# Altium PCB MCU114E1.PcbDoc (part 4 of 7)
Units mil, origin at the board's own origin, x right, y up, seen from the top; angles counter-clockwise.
Board outline 4163.97 x 2322.49 mil, 8 copper layers (Top Layer, GND 2, Signal Layer 3, Power 4, Power 5, Signal Layer 6, GND 7, Bottom), stack 61.2 mil thick; 444 components, 416 nets, 1812 pads, 989 vias.
Unrouted connection lines stored in the file: 3.
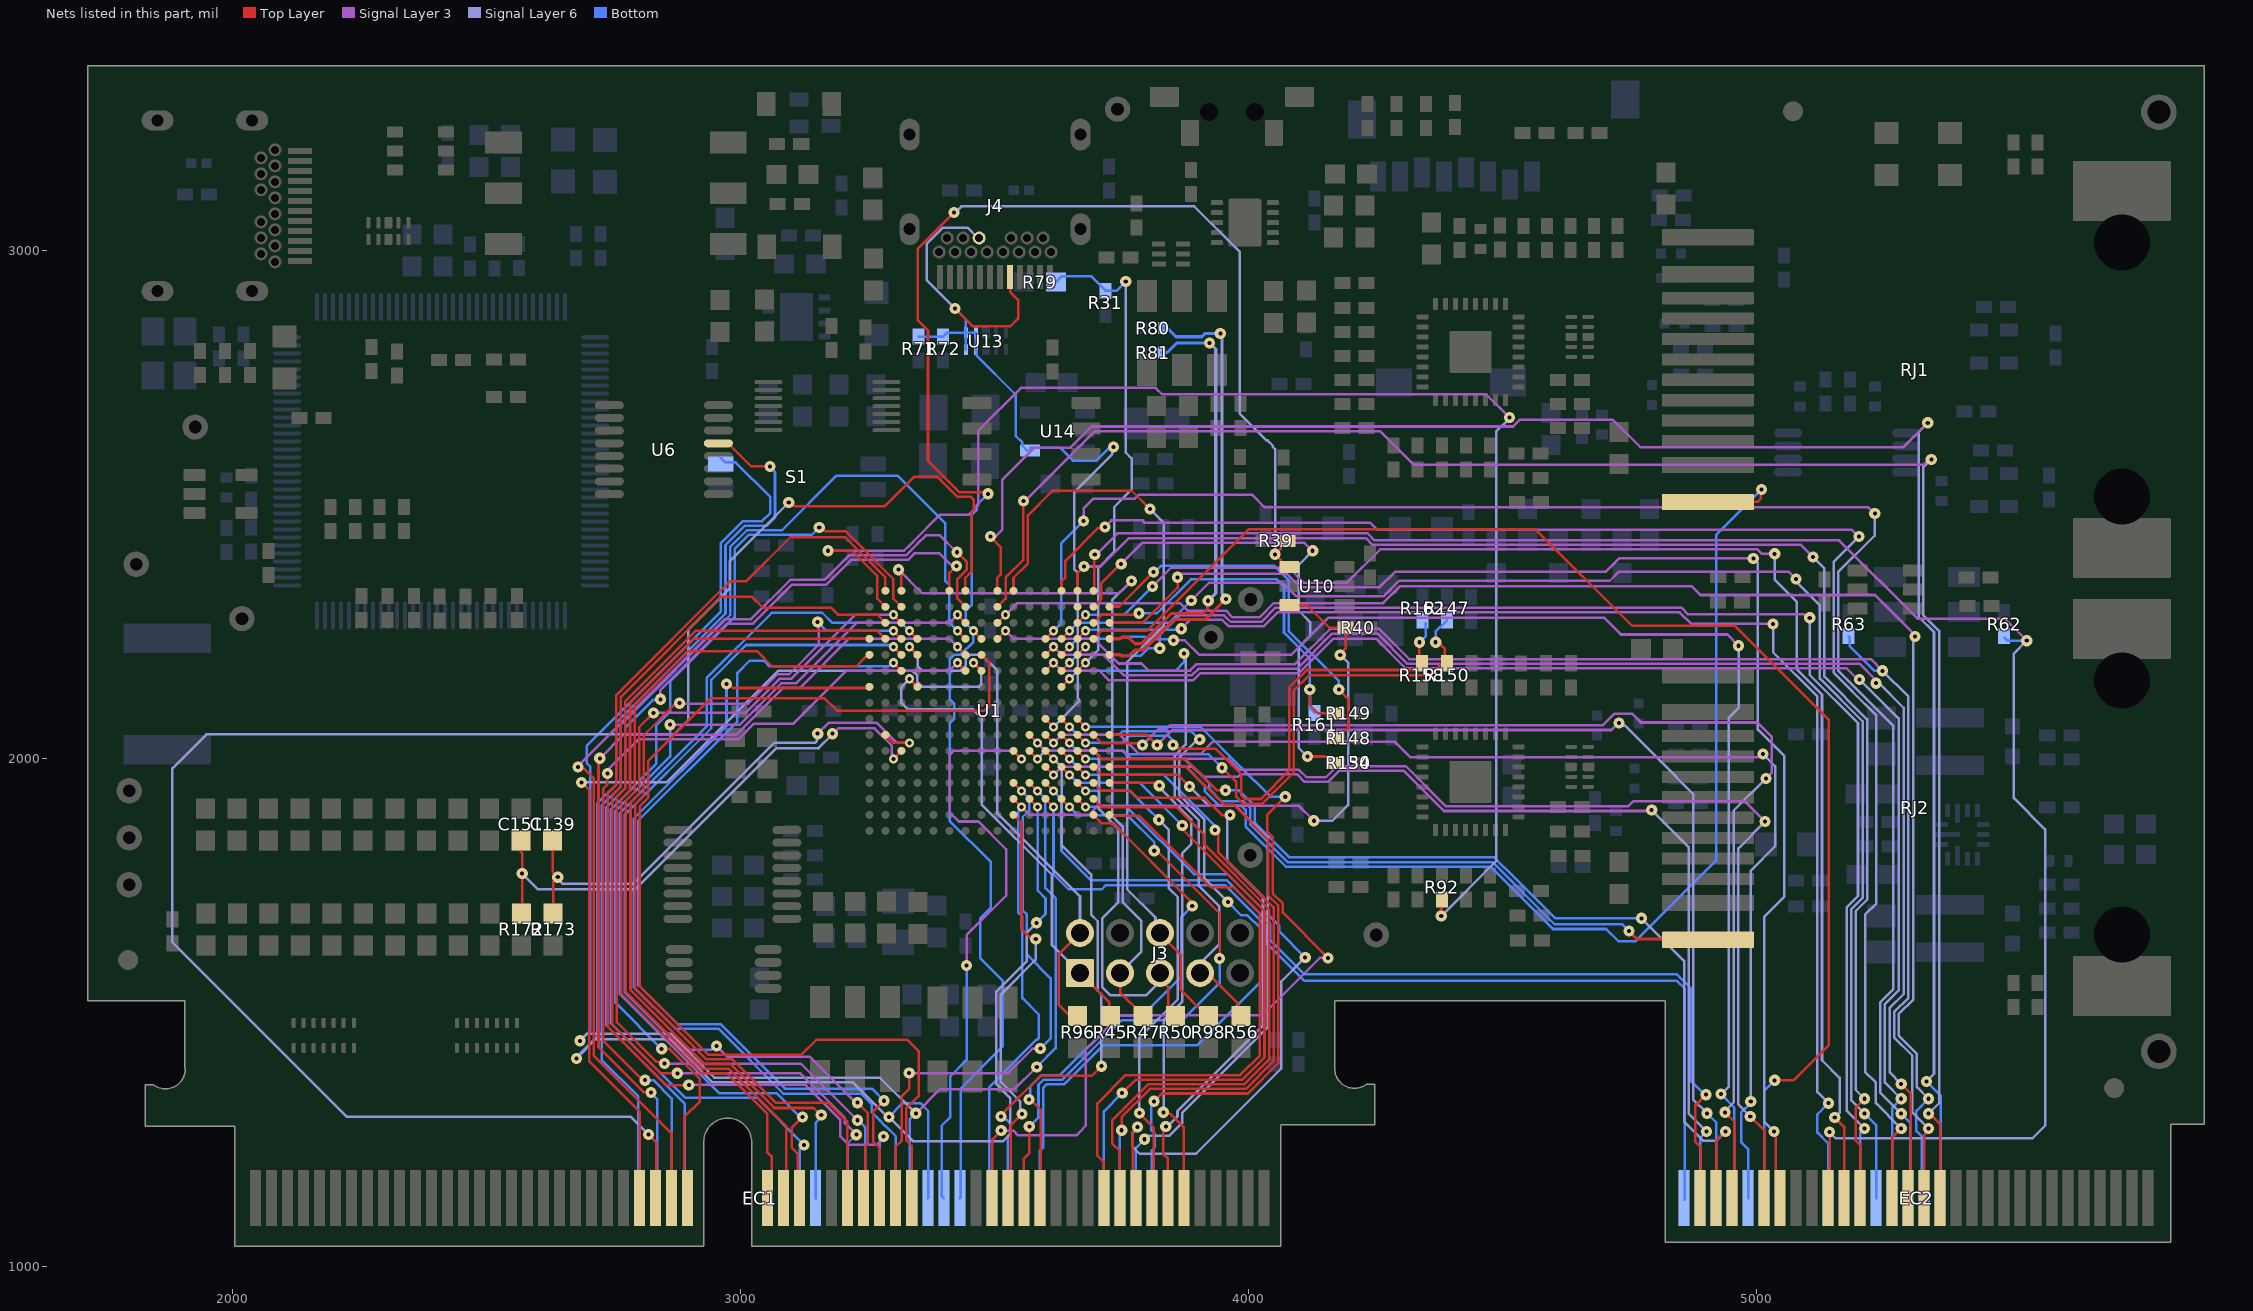
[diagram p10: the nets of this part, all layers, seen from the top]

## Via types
v1: diameter 22, hole 8, Top Layer to Bottom, tented both sides, 818 vias
v2: diameter 18, hole 8, Top Layer to Bottom, tented both sides, 153 vias
v3: diameter 19.68, hole 7.87, Top Layer to Bottom, 18 vias

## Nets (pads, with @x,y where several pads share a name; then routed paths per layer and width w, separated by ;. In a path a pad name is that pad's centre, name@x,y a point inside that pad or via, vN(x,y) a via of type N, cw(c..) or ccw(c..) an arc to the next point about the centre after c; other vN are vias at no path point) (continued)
MCU_C10C11_N: C139.1 R173.1 U1.K2 | length 1059.9
  Top Layer w4.9: C139.1@2630.06,1839.38 2630.06,1777.12 v1(2640.31,1766.88) 2631.04,1757.6 R173.1@2631.04,1695.94 ; U1.K2@3285.09,2047.04 3301.08,2031.06 v2(3332.6,2031.06)
  Signal Layer 3 w4.9: v1(3151.82,2049.25) 3173.14,2070.57 3268.21,2070.57 3307.73,2031.06 v2(3332.6,2031.06)
  Signal Layer 6 w4.9: v1(2640.31,1766.88) 2640.31,1763.7 2649.67,1754.34 2789.09,1754.34 3066.57,2031.82 3089.6,2031.82 3147.36,2031.82 3150.23,2034.69 3150.23,2047.67 v1(3151.82,2049.25)
MCU_C10C11_P: C151.1 R172.1 U1.L3 | length 1079.9
  Top Layer w4.9: C151.1@2567.97,1839.38 2567.97,1816.69 2570.31,1814.36 v1(2570.31,1773.88) 2570.31,1697.31 R172.1@2568.95,1695.94
  Top Layer w5: v2(3300.84,1999.8) U1.L3@3316.59,2015.55
  Signal Layer 3 w4.9: v1@3180.82,2048.25 3192.24,2059.67 3263.7,2059.67 3297.81,2025.56 3297.81,2009.22 3298.34,2008.69 3298.34,2003.35 3297.81,2002.83 v2(3300.84,1999.8)
  Signal Layer 6 w4.9: v1(2570.31,1773.88) 2600.74,1743.44 2793.61,1743.44 3071.08,2020.92 3085.09,2020.92 3153.48,2020.92 v1@3180.82,2048.25
  other v1: 3180.82,2049.25
MCU_D_N: R81.2 U1.D16 | length 864
  Top Layer w6.1: U1.D16@3726.04,2236.02 3746.91,2236.02 3749.21,2238.32 3764.16,2238.32 3776.16,2226.32 3788.14,2226.32 3847.73,2285.91 3909.36,2285.91 3919.09,2295.64 3919.09,2309.75 v1(3920.19,2310.85)
  Signal Layer 6 w6.1: v1(3920.19,2310.85) 3935,2325.66 3935,2806.1 v1(3922.83,2818.27)
  Bottom w6.1: R81.2@3828.72,2799.19 3839.64,2799.19 3858.72,2818.27 v1(3922.83,2818.27)
MCU_D_P: R80.2 U1.E16 | length 928
  Top Layer w6.1: U1.E16@3726.04,2204.52 3746.91,2204.52 3749.21,2202.22 3764.16,2202.22 3776.16,2214.22 3793.15,2214.22 3852.74,2273.81 3914.37,2273.81 v1(3954.83,2314.27)
  Signal Layer 6 w6.1: v1(3944,2836.98) 3947.1,2833.88 3947.1,2325.79 3954.83,2318.06 v1(3954.83,2314.27)
  Bottom w6.1: R80.2@3829.09,2847.19 3840.02,2847.19 3856.84,2830.37 3907.83,2830.37 3908.08,2830.56 3914.51,2836.98 v1(3944,2836.98)
MCU_GPIO0: EC1.49 U1.F8 | length 1837.1
  Top Layer w5: v1(2687,1953) 2688.3,1953 2702.5,1938.8 2702.5,1404.5 2801.46,1305.54 2801.46,1268.02 2801.33,1267.89 2801.33,1253.39 2801.46,1253.27 EC1.49@2801.46,1135.27 ; v2(3458.32,2188.77) U1.F8@3474.07,2173.03
  Signal Layer 6 w5: v1(2687,1953) 2687.5,1953.5 2854.54,1953.5 3073.82,2172.78 3338.76,2172.78 3347.84,2163.7 3347.84,2151.35 3357.41,2141.78 3411.08,2141.78 3411.33,2141.53 3468.89,2141.53 3473.82,2146.46 3473.82,2173.27 v2(3458.32,2188.77)
MCU_GPIO1: EC1.51 U1.A7 | length 3729.6
  Top Layer w5: v1(2818.83,1260.64) 2834.33,1245.14 2834.33,1135.27 EC1.51@2832.95,1135.27 ; v1(3094.83,2504.27) 3098.99,2504.27 3106.26,2497 3284,2497 3342,2555 3387,2555 3426.23,2515.77 3452.4,2515.77 3459.33,2508.84 3459.33,2490.25 3454.65,2485.56 3454.65,2368.17 3442.57,2356.1 U1.A7@3442.57,2330.51
  Signal Layer 6 w5: v1(2818.83,1260.64) 2784.21,1295.27 2225.26,1295.27 1882,1638.53 1882,1981 1949,2048 2869.15,2048 2897.33,2076.18 2897.33,2253.92 2978.5,2335.09 2978.5,2387.94 v1(3094.83,2504.27)
MCU_GPIO2: EC1.53 U1.B7 | length 2009.5
  Top Layer w5: v1(2680,1984) 2683.25,1980.75 2692.25,1980.75 2711.5,1961.5 2711.5,1415.5 2864.45,1262.55 EC1.53@2864.45,1135.27 ; v1(3425.83,2406.27) 3445.33,2386.77 3445.33,2372.77 3426.54,2353.98 3426.54,2315.04 U1.B7@3442.57,2299.01
  Signal Layer 3 w5: v1(2680,1984) 2680,1985.56 2969.21,2274.77 3002.33,2274.77 3020.85,2274.77 3097.85,2351.77 3165.13,2351.77 3213.63,2400.27 3325.75,2400.27 3348.5,2423.02 3348.5,2423.21 3364.79,2439.5 3392.25,2439.5 3425.48,2406.27 v1(3425.83,2406.27)
MCU_GPIO3: EC1.55 U1.C7 | length 1747.5
  Top Layer w5: v1(2844.83,1429.27) 2860.58,1429.27 2920,1369.85 2920,1325.73 2889,1294.73 2889,1142.21 EC1.55@2895.94,1135.27 ; v2(3426.83,2283.26) U1.C7@3442.57,2267.52
  Signal Layer 3 w5: v1(2861.26,2067.05) 2998.9,2067.05 3080.12,2148.27 3109.08,2148.27 3228.08,2267.27 3410.83,2267.27 v2(3426.83,2283.26)
  Bottom w5: v1(2844.83,1429.27) 2753.73,1520.37 2753.73,1896.82 2861.26,2004.35 v1(2861.26,2067.05)
MCU_GPIO4: EC1.50 U1.D7 | length 2181.2
  Top Layer w5: v2(3426.83,2251.77) U1.D7@3442.57,2236.02
  Bottom w5: EC1.50@2801.46,1135.27 2798.94,1137.78 2798.94,1335.06 2726.73,1407.27 2726.73,1908 2764.5,1945.77 2764.5,2067.41 2979.37,2282.29 2979.37,2416.64 3012.3,2449.57 3081.57,2449.57 3189.24,2557.24 3308.6,2557.24 3403,2462.85 3403,2349.53 3410.83,2341.7 3410.83,2267.76 v2(3426.83,2251.77)
MCU_GPIO5: EC1.52 U1.E7 | length 1755.1
  Top Layer w5: v1(2723.04,2000.8) 2720.5,1998.25 2720.5,1432.5 2808.92,1344.08 2822.92,1344.08 v1(2824,1343) ; v1@2724.26,1999.58 v1@2724.78,2000.1 ; v2(3426.83,2220.27) U1.E7@3442.57,2204.52
  Signal Layer 3 w5: v1(2723.04,2000.8) 2769.51,2047.27 2786.41,2047.27 2991.84,2047.27 3083.84,2139.27 3116.83,2139.27 3213.83,2236.27 3294.42,2236.27 3410.83,2236.27 v2(3426.83,2220.27)
  Bottom w5: v1(2824,1343) 2824,1341.5 2836.33,1329.17 2836.33,1138.65 EC1.52@2832.95,1135.27
MCU_GPIO6: EC1.54 U1.F7 | length 1712.7
  Top Layer w5: v1(2738,1971) 2738,1949.5 2729.5,1941 2729.5,1445.23 2807.26,1367.47 v1(2812.24,1367.47) ; v2(3426.83,2188.77) U1.F7@3442.57,2173.03
  Signal Layer 3 w5: v1(2738,1971) 2738,1977.44 2798.83,2038.27 2995.57,2038.27 3026.57,2069.27 3104.25,2069.27 3208.26,2173.27 3411.33,2173.27 v2(3426.83,2188.77)
  Bottom w5: v1(2812.24,1367.47) 2828.53,1367.47 2864.45,1331.55 EC1.54@2864.45,1135.27
MCU_GPIO7: EC1.56 U1.A6 | length 1876.8
  Top Layer w5: U1.A6@3411.08,2330.51 3411.08,2365.52 v1(3424.83,2379.27)
  Signal Layer 3 w5: v1(2842.32,2116.95) 2842.32,2135.14 2972.94,2265.77 3024.58,2265.77 3101.58,2342.77 3168.86,2342.77 3217.36,2391.27 3329.47,2391.27 3342.2,2404 3391.42,2404 3412.9,2382.52 3421.58,2382.52 v1(3424.83,2379.27)
  Bottom w5: v1(2842.32,2116.95) 2840.92,2115.55 2827.55,2115.55 2773.5,2061.5 2773.5,1942.04 2735.73,1904.27 2735.73,1475.64 2890,1321.37 2890,1141.21 EC1.56@2895.94,1135.27
MCU_GPIO8: EC1.57 U1.D1 | length 1660.3
  Top Layer w5: EC1.57@3053.43,1135.27 3061,1142.84 3061,1217.64 3052.13,1226.51 3052.13,1301.87 2972.73,1381.27 2921.82,1381.27 2765.5,1537.59 2765.5,1921.32 2782.5,1938.32 2782.5,2109.77 2908.75,2236.02 U1.D1@3253.6,2236.02
MCU_GPIO9: EC1.59 U1.E1 | length 1668.2
  Top Layer w5: EC1.59@3084.92,1135.27 3090.33,1140.68 3090.33,1276.4 2976.46,1390.27 2925.55,1390.27 2774.5,1541.32 2774.5,1917.59 2791.5,1934.59 2791.5,2106.04 2897.1,2211.65 3032.66,2211.65 3062.31,2182 3221.83,2182 3227.78,2182.03 3246.06,2200.31 3246.48,2200.31 3250.69,2204.52 U1.E1@3253.6,2204.52
MCU_GPIO10: EC1.61 U1.D4 | length 1816
  Top Layer w5: EC1.61@3116.42,1135.27 3112.83,1138.85 3112.83,1222.27 3100.83,1234.27 3100.83,1238.41 3100.83,1274.27 v1(3121.83,1295.27) ; v2(3332.34,2251.77) U1.D4@3348.09,2236.02
  Bottom w5: v1(3121.83,1295.27) 3117.23,1295.27 3070.5,1342 2958,1342 2762.73,1537.27 2762.73,1893.09 2933.33,2063.69 2933.33,2158.97 3061.63,2287.27 3160.83,2287.27 3180.59,2267.51 3316.59,2267.51 v2(3332.34,2251.77)
MCU_GPIO11: J3.2 R96.2 U1.E4 | length 1047.5
  Top Layer w5: v2(3332.34,2220.27) U1.E4@3348.09,2204.52 ; R96.2@3663.44,1497.68 3644.44,1497.68 3626,1516.12 3626,1615.09 J3.2@3667.96,1657.05
  Signal Layer 6 w5: v2(3332.34,2220.27) 3348.33,2204.27 3348.33,2182.35 3357.41,2173.27 3379.33,2173.27 3433.25,2173.27 3442.82,2182.85 3442.82,2195.19 3451.9,2204.27 3474.32,2204.27 3505.32,2173.27 3505.32,1891.99 3667.96,1729.35 J3.2@3667.96,1657.05
MCU_GPIO12: J3.1 R45.1 U1.G4 | length 931.4
  Top Layer w5: v2(3332.34,2157.28) U1.G4@3348.09,2141.53 ; J3.1@3667.96,1578.31 3725.59,1520.68 R45.1@3725.59,1499.18
  Signal Layer 6 w5: v2(3332.34,2157.28) 3316.59,2141.53 3316.59,2110.03 3329.57,2097.06 3457.83,2097.06 3474.32,2080.57 3474.32,1910.26 3612.83,1771.75 3612.83,1633.44 J3.1@3667.96,1578.31
MCU_GPIO13: J3.3 R47.1 U1.A3 | length 1456
  Top Layer w5: v1(3311,2372) 3316.59,2366.41 U1.A3@3316.59,2330.51 ; R47.1@3787.8,1499.18 3746.7,1540.28 J3.3@3746.7,1578.18 ; J3.3@3746.7,1578.18 cw(c3838.52,1578.31) J3.3@3746.7,1578.31 J3.3@3746.7,1578.18
  Signal Layer 3 w5: v1(3311,2372) 3357.41,2325.59 3744.59,2325.59 v1(3769,2350)
  Signal Layer 6 w5: J3.3@3746.7,1578.31 3788.83,1620.44 3788.83,1680.93 3751.93,1717.83 3751.93,1866.87 3731.31,1887.49 3731.31,2312.31 v1(3769,2350)
MCU_GPIO14: EC1.62 U1.B3 | length 2055.1
  Top Layer w5: v1(3154.83,2455.27) 3158.99,2455.27 3166.26,2448 3206.1,2448 3300.47,2353.63 3300.47,2315.13 U1.B3@3316.59,2299.01
  Bottom w5: EC1.62@3116.42,1135.27 3116.42,1231.85 v1(3124.83,1240.27) 3032.1,1333 2891.1,1333 2744.73,1479.37 2744.73,1900.55 2834,1989.82 2834,2065.44 2861.33,2092.77 2861.33,2151.52 2988.37,2278.56 2988.37,2412.91 3016.03,2440.57 3140.13,2440.57 v1(3154.83,2455.27)
MCU_GPIO15: EC1.64 U1.C3 | length 1783.9
  Top Layer w5: v1(2828.83,2090.27) 2800.5,2061.94 2800.5,1930.86 2783.5,1913.86 2783.5,1545.04 2929.28,1399.27 2980.19,1399.27 3066.69,1312.77 3144.08,1312.77 3157.58,1299.27 v1(3158.83,1299.27) ; v2(3300.84,2283.26) U1.C3@3316.59,2267.52
  Signal Layer 3 w5: v1(2828.83,2090.27) 3009.39,2090.27 3076.39,2157.27 3099.58,2157.27 3225.58,2283.26 v2(3300.84,2283.26)
  Bottom w5: EC1.64@3147.91,1135.27 3148.33,1135.69 3148.33,1284.17 3158.83,1294.67 v1(3158.83,1299.27)
MCU_GPIO16: EC1.67 U1.D3 | length 1825.3
  Top Layer w5: v1(2879.83,2109.27) 2876.58,2106.02 2869.33,2106.02 2809.5,2046.19 2809.5,1927.13 2792.5,1910.13 2792.5,1548.77 2933,1408.27 2983.92,1408.27 3069.42,1322.77 3173.33,1322.77 3209.71,1286.39 3209.71,1136.47 EC1.67@3210.91,1135.27 ; v2(3300.84,2251.77) U1.D3@3316.59,2236.02
  Signal Layer 3 w5: v1(2879.83,2109.27) 2880.83,2108.27 3014.66,2108.27 3072.66,2166.27 3095.85,2166.27 3153.83,2224.25 3153.83,2267.27 v1(3151.83,2269.27)
  Bottom w5: v1(3151.83,2269.27) 3169.33,2251.77 v2(3300.84,2251.77)
MCU_GPIO17: EC1.69 U1.E3 | length 1850.2
  Top Layer w5: v1(3229.83,1323.27) 3250.33,1302.77 3250.33,1242.27 3245.33,1237.27 3245.33,1138.2 EC1.69@3242.4,1135.27 ; v2(3300.84,2220.27) U1.E3@3316.59,2204.52
  Signal Layer 3 w5: v1(2953,1435) 2974.73,1413.27 3136.28,1413.27 3226.28,1323.27 v1(3229.83,1323.27)
  Bottom w5: v1(2953,1435) 2949.57,1435 2941.57,1427 2885.73,1427 2771.73,1541 2771.73,1889.36 2942.33,2059.96 2942.33,2155.24 3010.86,2223.77 3291.41,2223.77 3292.42,2222.76 3298.35,2222.76 v2(3300.84,2220.27)
MCU_GPIO18: EC1.71 U1.F3 | length 1825.1
  Top Layer w5: EC1.71@3273.9,1135.27 3273.9,1233.72 3260.83,1246.79 3260.83,1305.88 v1(3282.03,1327.07) ; v2(3300.84,2188.77) U1.F3@3316.59,2173.03
  Bottom w5: v1(3282.03,1327.07) 3258.33,1350.77 3087.19,1350.77 2960.19,1477.77 2875.72,1477.77 2798.73,1554.76 2798.73,1878.18 2993.83,2073.28 2993.83,2168.83 3017.77,2192.77 3046.08,2192.77 3057.07,2181.78 3291.41,2181.78 3298.41,2188.77 v2(3300.84,2188.77)
MCU_GPIO19: R92.2 U1.B2 | length 2839
  Top Layer w5: v1(3171.83,2409.27) 3219.38,2409.27 3268.97,2359.67 3268.97,2315.13 U1.B2@3285.09,2299.01
  Top Layer w6.25: v1(4378.83,1690.27) 4378.83,1722.1 R92.2@4379.8,1723.06
  Signal Layer 3 w5: v1(3171.83,2409.27) 3321.83,2409.27 3329.06,2416.5 3329.25,2416.5 3339.5,2426.75 3339.5,2426.94 3392.83,2480.27 3449.35,2480.27 3467.33,2498.25 3467.33,2645.33 3551.84,2729.84 3816.77,2729.84 3829.85,2716.77 4467.33,2716.77 v1(4512.83,2671.27)
  Signal Layer 6 w5: v1(4378.83,1690.27) 4486.83,1798.27 4486.83,2643.84 4512.83,2669.84 v1(4512.83,2671.27)
MCU_GPIO20: EC1.68 U1.C2 | length 1983.9
  Top Layer w5: v1(2875.55,1380.99) 2843.11,1380.99 2747.5,1476.6 2747.5,1928.77 2764.5,1945.77 2764.5,2121.5 2962.07,2319.07 3021.85,2319.07 3043.73,2297.19 3178.09,2297.19 3191.63,2283.64 3268.97,2283.64 U1.C2@3285.09,2267.52
  Signal Layer 3 w5: v1(2875.55,1380.99) 3117.74,1380.99 3205.13,1293.6 3205.13,1282.97 v1(3227.81,1260.29)
  Bottom w5: EC1.68@3210.91,1135.27 3210.91,1243.38 v1(3227.81,1260.29)
MCU_GPIO21: EC1.70 U1.D2 | length 1929.6
  Top Layer w5: v1(2850.28,1400.27) 2847.03,1403.52 2834.48,1403.52 2756.5,1481.5 2756.5,1925.04 2773.5,1942.04 2773.5,2113.5 2911.39,2251.39 3269.72,2251.39 U1.D2@3285.09,2236.02
  Signal Layer 3 w5: v1(2850.28,1400.27) 3118.5,1400.27 v1(3230.08,1288.69)
  Bottom w5: v1(3230.08,1288.69) 3231.91,1288.69 3245.31,1275.29 3245.31,1138.18 EC1.70@3242.4,1135.27
MCU_GPIO22: EC1.72 U1.A2 | length 2168.4
  Top Layer w5: v1(2898.25,1358.07) 2897.87,1357.69 2853.69,1357.69 2747,1464.37 2738.5,1472.87 2738.5,1932.5 2755.5,1949.5 2755.5,2125.23 2979.73,2349.46 3011.55,2349.46 3097.85,2435.77 3205.6,2435.77 3285.09,2356.28 U1.A2@3285.09,2330.51
  Signal Layer 3 w5: v1(2898.25,1358.07) 3127.93,1358.07 3196.13,1289.87 3196.13,1257.97 3213.83,1240.27 3268.85,1240.27 3281.36,1252.78 v1(3281.36,1256.8)
  Bottom w5: EC1.72@3273.9,1135.27 3273.9,1249.34 v1(3281.36,1256.8)
MCU_GPIO23: EC1.74 U1.G1 | length 1725.4
  Top Layer w5: v1(2972.4,2146.85) 2977,2146.85 2984.67,2139.19 3245.3,2139.19 3245.58,2139.47 3251.54,2139.47 U1.G1@3253.6,2141.53
  Bottom w5: v1(2972.4,2146.85) 2972.4,2064.58 2789.73,1881.91 2789.73,1551.03 2871.99,1468.77 2956.46,1468.77 3084.46,1340.77 3237.08,1340.77 3258.21,1319.64 3258.21,1304.71 3274.33,1288.58 3274.33,1288.02 3284.58,1277.77 3285.15,1277.77 3305.39,1257.52 EC1.74@3305.39,1135.27
MCU_GPIO24: EC1.75 U1.E8 | length 2224.1
  Top Layer w5: EC1.75@3336.89,1135.27 3336.89,1238.21 3325.83,1249.27 3325.83,1311.76 3350.29,1336.23 3350.29,1424.87 3328.16,1447 3149,1447 3119.27,1417.27 2936.73,1417.27 2801.5,1552.5 2801.5,1906.41 2818.5,1923.4 2818.5,1996.24 2941.03,2118.77 3165.23,2118.77 3189.47,2094.53 3221.64,2094.53 3221.77,2094.66 3480.44,2094.66 3489.44,2103.67 3489.44,2189.15 U1.E8@3474.07,2204.52
MCU_GPIO25: J3.6 R98.2 U1.A10 | length 1531.5
  Top Layer w5: U1.A10@3537.06,2330.51 3537.06,2356.1 3565.33,2384.37 3565.33,2479.02 3613.58,2527.27 3769.83,2527.27 v1(3805.83,2491.27) ; J3.6@3825.44,1657.05 3825.44,1654.68 3866.44,1613.68 3866.44,1545.03 R98.2@3912.29,1499.18
  Signal Layer 6 w5: v1(3805.83,2491.27) 3833,2464.1 3833,2262.56 3760.93,2190.5 3760.93,1743.07 3816.54,1687.46 3816.54,1665.95 J3.6@3825.44,1657.05
MCU_GPIO26: J3.5 R50.1 U1.L11 | length 876.4
  Top Layer w5: U1.L11@3568.56,2015.55 v2(3584.31,1999.8) ; J3.5@3825.44,1578.31 3825.44,1566.91 3841.83,1550.52 3841.83,1505.27 R50.1@3849.42,1497.68
  Signal Layer 6 w5: v2(3584.31,1999.8) 3600.3,2015.79 3694.79,2015.79 3705.31,2005.28 3705.31,1900.77 3742.93,1863.14 3742.93,1717.37 3711.83,1686.27 3711.83,1550.27 3727.83,1534.27 3797.83,1534.27 3825.44,1561.88 J3.5@3825.44,1578.31
MCU_GPIO27: J3.7 R56.1 U1.G13 | length 1096.4
  Top Layer w5: U1.G13@3631.55,2141.53 v2(3647.3,2157.28) ; J3.7@3904.18,1578.31 3913.69,1568.8 3928.3,1568.8 3979.08,1518.02 3979.08,1499.52 R56.1@3984.83,1493.76
  Signal Layer 6 w5: v1(3872.83,2207.27) 3875.92,2204.18 3875.92,2027.61 3854,2005.69 3854,1926.12 3868.33,1911.79 3902,1878.12 3902,1750 3941.83,1710.17 3941.83,1675.27 ; J3.7@3904.18,1578.31 3904.18,1597.06 3941.82,1634.69 3941.82,1675.26
  Bottom w5: v2(3647.3,2157.28) 3662.74,2172.72 3672.31,2172.72 3672.37,2172.78 3830.57,2172.78 ; 3830.58,2172.77 3855.52,2172.77 3872.83,2190.08 v1(3872.83,2207.27)
MCU_GPIO28: EC1.76 S1.2 U1.N11 | length 3163.7
  Top Layer w5: U1.N11@3568.56,1952.55 v2(3584.31,1936.81)
  Signal Layer 3 w5: v1(3344.83,1302.27) 3392.56,1350 3539.19,1350 v1(3582.87,1393.69)
  Signal Layer 6 w5: v1(2684,1445) 2698,1459 2861.83,1459 2948.56,1372.27 3274.83,1372.27 v1(3344.83,1302.27) ; v1(3582.87,1393.69) 3581.87,1392.69 3581.87,1393.69 v1@3582.87,1394.69
  Bottom w5: v1(2684,1445) 2704.5,1465.5 2704.5,1984.25 2697,1991.75 2697,2025.37 2961.37,2289.74 2961.37,2424.09 3004.85,2467.57 3042.59,2467.57 3058.83,2483.8 3058.83,2514.83 2990.44,2583.22 2970.34,2583.22 S1.2@2960.87,2592.69 ; EC1.76@3336.89,1135.27 3333.33,1138.83 3333.33,1290.77 v1(3344.83,1302.27) ; v1(3582.87,1393.69) 3620,1430.81 3620,1725.56 3599.87,1745.69 3599.87,1762.69 ; v2(3584.31,1936.81) 3599.81,1921.31 3599.81,1762.69
MCU_GPIO29: EC1.78 U1.P11 U6.13 | length 3425.7
  Top Layer w5: U6.13@2956.44,2620.69 2958.5,2618.63 2977.74,2618.63 3021.05,2575.32 3057.78,2575.32 v1(3057.83,2575.27) ; U1.P11@3568.56,1921.06 v2(3584.31,1905.31)
  Signal Layer 6 w5: v1(2677,1410) 2715,1448 2860.1,1448 2944.83,1363.27 3221.08,1363.27 3289.08,1295.27 v1(3291.83,1295.27) 3339.33,1247.77 3384.08,1247.77 3516.95,1247.77 3530.61,1261.42 3530.61,1332.43 3503.37,1359.66 3503.37,1542.37 3563.4,1602.4 3563.4,1658.21 v1(3582.37,1677.17)
  Bottom w5: v1(2677,1410) 2677,1413.25 2717.73,1453.98 2717.73,1911.73 2755.5,1949.5 2755.5,2071.14 2970.37,2286.01 2970.37,2420.37 3008.57,2458.57 3051.65,2458.57 3067.83,2474.75 3067.83,2563.84 3057.83,2573.84 v1(3057.83,2575.27) ; v1(3291.83,1295.27) 3318.83,1322.27 3353.84,1322.27 3369.33,1306.78 3369.33,1260.02 3369.33,1136.21 EC1.78@3368.39,1135.27 ; v1(3582.37,1677.17) 3600.06,1694.86 3600.06,1725.04 3584.87,1740.23 3584.87,1760.29 3584.65,1760.51 3584.65,1904.96 v2(3584.31,1905.31)
MCU_GPIO30: EC1.80 U1.L10 | length 1168.6
  Top Layer w5: U1.L10@3537.06,2015.55 v2(3552.81,1999.8)
  Signal Layer 3 w5: v1(3444.83,1593.27) 3444.83,1652.87 3522.83,1730.87 3522.83,1821.54 3467.85,1876.52 3429.52,1876.52 3411.33,1894.71 3411.33,2007.7 3418.92,2015.3 3537.31,2015.3 v2(3552.81,1999.8)
  Bottom w5: EC1.80@3399.88,1135.27 3395.91,1139.24 3395.91,1277.98 3412.83,1294.9 3412.83,1375.27 3444.83,1407.27 v1(3444.83,1593.27)
MCU_GPIO31: EC1.82 R39.1 U1.D8 U10.1 | length 3544.8
  Top Layer w5: v1(3420,3075) 3348.33,3003.33 3348.33,2863.02 3368.83,2842.52 3368.83,2585.9 3429.96,2524.77 3483.33,2524.77 v1(3486.83,2521.27) ; v2(3458.32,2251.77) U1.D8@3474.07,2236.02 ; R39.1@4076.49,2428.69 4072.6,2428.69 4063.29,2419.37 4063.29,2413.73 v1(4051.83,2402.27) 4062.91,2391.19 4062.91,2386.4 4072.22,2377.09 U10.1@4079.74,2377.09
  Signal Layer 6 w5: v1(3420,3075) 3422.66,3075 3434.43,3086.77 3793.56,3086.77 3793.79,3087 3892.75,3087 3982,2997.75 3982,2679 4034.75,2626.25 4036.95,2626.25 4047.2,2616 4047.2,2613.8 4051.83,2609.17 v1(4051.83,2402.27)
  Bottom w5: EC1.82@3431.38,1135.27 3433.33,1137.22 3433.33,1351.41 3515.83,1433.91 3515.83,1563.27 3471.83,1607.27 3471.83,1686.45 3492.59,1707.21 3492.59,1796.51 3411.33,1877.77 3411.33,1911.73 3411.33,2069.21 3420.92,2078.8 3420.92,2108.2 3411.33,2117.79 3411.33,2195.19 3420.9,2204.77 3433.25,2204.77 3458.32,2229.85 v2(3458.32,2251.77) 3442.89,2267.2 3442.89,2276.78 3442.82,2276.84 3442.82,2289.68 3442.89,2289.75 3442.89,2290.31 3454.83,2302.26 3454.83,2479.27 3464.83,2489.27 3464.83,2499.27 v1(3486.83,2521.27)
MCU_GPIO32: EC1.85 U1.J14 | length 1883.2
  Top Layer w5: EC1.85@3495.44,1138.69 3495.44,1251 v1(3512.83,1268.39) ; U1.J14@3663.05,2078.54 v2(3678.79,2062.79) ; v1@4077.83,1931.27 4036,1889.44 4036,1857.35 4047,1846.35 4047,1734.99 4067,1714.99 4067,1697.01 v1(4155.91,1608.1)
  Signal Layer 3 w5: v1(3512.83,1268.39) 3536.71,1268.39 3546.33,1258.77 3660.77,1258.77 3670,1268 3679,1277.77 3679,1427.44 3746.83,1495.27 4026.83,1495.27 4139.66,1608.1 v1(4155.91,1608.1)
  Bottom w5: v2(3678.79,2062.79) 3905.53,2062.79 3986.15,1982.17 3986.15,1981.85 4011.66,1956.33 4011.99,1956.33 4043.05,1925.27 v1@4075.83,1925.27
  other v1: 4071.83,1925.27
MCU_GPIO33: EC1.87 U1.R10 | length 832
  Top Layer w5: EC1.87@3525.87,1135.27 3532.1,1141.5 3532.1,1279.54 v1(3553.83,1301.27) ; U1.R10@3537.06,1889.56 3552.81,1873.81 3552.81,1665.29 v1@3576.83,1641.27
  Signal Layer 6 w5: v1(3553.83,1301.27) 3550.33,1304.77 3550.33,1325.43 3512.37,1363.39 3512.37,1536.37 3580.9,1604.9 v1(3580.9,1645.35)
MCU_GPIO34: EC1.86 R40.1 U1.P10 U10.3 | length 2025.9
  Top Layer w5: U1.P10@3537.06,1921.06 v2(3552.81,1905.31) ; U10.3@4079.74,2302.28 4114.13,2302.28 4158.42,2258 R40.1@4190.66,2258 4190.66,2217.26 4180,2206.6 v1(4180,2204.3)
  Signal Layer 3 w5: v2(3552.81,1905.31) 3568.31,1889.81 3685.22,1889.81 3702.67,1907.27 4098.73,1907.27 v1(4128,1878)
  Signal Layer 6 w5: v1(4128,1878) 4164.56,1878 4195.33,1908.77 4195.33,2188.97 v1(4180,2204.3)
  Bottom w5: EC1.86@3494.37,1135.27 3488.96,1140.68 3488.96,1353.52 3582.62,1447.19 3584.07,1447.19 3587,1450.11 3587,1496.25 3554.4,1528.85 3554.4,1689.79 3546.31,1697.88 3546.31,1895.88 3552.81,1902.38 v2(3552.81,1905.31)
MCU_GPIO35: EC1.73 U1.N10 | length 1107.4
  Top Layer w5: EC1.73@3305.39,1135.27 3305.39,1236.83 3316.83,1248.27 3316.83,1335.27 3331.89,1350.33 v1(3331.89,1381.58) ; U1.N10@3537.06,1952.55 v2(3552.81,1936.81)
  Signal Layer 3 w5: v1(3331.89,1381.58) 3526.58,1381.58 3574.3,1429.3 3589.49,1429.3 v1(3589.87,1429.69)
  Bottom w5: v2(3552.81,1936.81) 3568.31,1921.31 3568.31,1911.73 3568.31,1898.89 3555.31,1885.89 3555.31,1701.61 3563.4,1693.51 3563.4,1665.81 3563.4,1614.6 3610,1568 3610,1449.81 v1(3589.87,1429.69)
MCU_GPIO36: EC2.122 U1.P12 | length 1930.9
  Top Layer w5: U1.P12@3600.06,1921.06 v2(3615.8,1905.31)
  Bottom w5: v2(3615.8,1905.31) 3615.8,1772.76 3645.37,1743.19 3711,1743.19 3719.08,1751.27 3953.56,1751.27 4033,1671.83 4033,1639.27 4109.27,1563 4842.56,1563 4857.87,1547.69 EC2.122@4857.87,1132.69
MCU_GPIO37: EC2.123 U1.N12 | length 1953.6
  Top Layer w5: U1.N12@3600.06,1952.55 v2(3615.8,1936.81) ; EC2.123@4889.05,1138.69 4889.05,1236.05 4878.83,1246.27 4878.83,1317.83 v1(4900,1339)
  Bottom w5: v2(3615.8,1936.81) 3631.55,1921.06 3631.55,1818.76 3689.62,1760.69 3956.87,1760.69 4042,1675.56 4042,1643 4109.31,1575.69 4842.6,1575.69 4870.83,1547.45 4870.83,1364.53 4896.36,1339 v1(4900,1339)
MCU_GPIO38: EC2.124 U1.M12 | length 2069.2
  Top Layer w5: U1.M12@3600.06,1984.05 v2(3615.8,1968.3)
  Signal Layer 3 w5: v2(3615.8,1968.3) 3631.3,1983.8 3891.55,1983.8 3910.58,1964.77 3979.6,1964.77 3984.6,1969.77 4094.54,1969.77 4109.71,1954.61 4155.64,1954.61 4177.31,1976.27 4305.29,1976.27 4384.37,1897.19 4782.75,1897.19 v1@4783.83,1898.27
  Signal Layer 6 w5: v1(4792.83,1899.27) 4865.57,1826.53 4865.57,1301.53 v1(4900.83,1266.27)
  Bottom w5: EC2.124@4887.98,1135.27 4887.98,1253.41 v1(4900.83,1266.27)
MCU_GPIO39: EC1.88 U1.L12 | length 1079
  Top Layer w5: v1(3512.53,1295.76) 3512.53,1298.72 3590,1376.19 3691.19,1376.19 v1(3710,1395) ; U1.L12@3600.06,2015.55 v2(3615.8,1999.8)
  Signal Layer 6 w5: v2(3615.8,1999.8) 3631.8,1983.8 3631.8,1830.45 3689.83,1772.41 3689.83,1693.27 3702.83,1680.27 3702.83,1543.52 3710,1536.35 v1(3710,1395)
  Bottom w5: v1(3512.53,1295.76) 3517.34,1295.76 3517.34,1295.55 3522.89,1290 ; 3522.94,1290 3530.33,1282.61 3530.33,1261.15 3525.87,1256.68 EC1.88@3525.87,1135.27
MCU_GPIO40: EC1.89 U1.P13 | length 1226.7
  Top Layer w5: EC1.89@3557.36,1135.27 3557.36,1213.27 3568.21,1224.11 v1(3568.21,1276.27) ; U1.P13@3631.55,1921.06 v2(3647.3,1905.31) ; v1(3814,1819) 3819.6,1819 3942.68,1695.92 v1(3942.68,1607.18)
  Bottom w5: v1(3568.21,1276.27) 3568.58,1276.27 3586.33,1294.02 3586.33,1358.96 3595.64,1368.27 3632.56,1368.27 3750.09,1485.8 3870.04,1485.8 3942.68,1558.45 v1(3942.68,1607.18) ; v2(3647.3,1905.31) 3663.36,1889.25 3760.75,1889.25 3814,1836 v1(3814,1819)
MCU_GPIO41: EC1.91 U1.R15 | length 1028.4
  Top Layer w5: v1(3567.83,1329.27) 3570.33,1329.27 3590.33,1309.27 3590.33,1136.74 EC1.91@3588.86,1135.27 ; U1.R15@3694.54,1889.56 3710.67,1873.44 3732.41,1873.44 v1@3885.58,1720.27
  Bottom w5: v1(3567.83,1329.27) 3569.95,1331.39 3569.95,1355.31 3577.33,1362.69 3591.91,1377.27 3628.83,1377.27 3746.37,1494.8 3791.23,1494.8 3867.57,1571.14 3867.57,1689.01 v1(3888.83,1710.27)
MCU_GPIO44: J4.A5 J4.B5 R71.1 R72.2 U1.J12 U13.4 U13.5 U13.6 U13.7 U14.4 | length 1800.4
  Top Layer w5: v1(3422,2886) 3457.35,2850.65 3530.65,2850.65 3546,2866 3546,2903 3530.53,2918.47 J4.A5@3530.53,2947.46 ; U1.J12@3600.06,2078.54 v2(3615.8,2062.79)
  Signal Layer 6 w5: v1(3422,2886) 3366,2942 3366,3012.82 3392.17,3038.99 3398.11,3044.93 3446.41,3044.93 3466.71,3024.63 J4.B5@3469.5,3024.63 ; v2(3615.8,2062.79) 3666.53,2113.51 3666.53,2116.13 3663.29,2119.36 3663.29,2366.06 3656.33,2373.02 3656.33,2524.26 3731.79,2599.72 3731.79,2611.39 v1(3734.04,2613.64)
  Bottom w5: R71.1@3350.58,2830.54 R72.2@3398.58,2830.54 3406.03,2838 U13.6@3443.32,2838 ; v1(3422,2886) 3443.32,2864.69 U13.6@3443.32,2838 ; U13.5@3443.32,2805.13 U13.6@3443.32,2838 ; U14.4@3563.71,2606.6 3554.4,2615.91 3554.4,2622.06 3541.5,2634.96 3541.5,2716.25 3464.44,2793.31 3464.44,2803.69 U13.4@3463,2805.13 U13.7@3463,2838 U13.6@3443.32,2838 ; U14.4@3569.87,2606.6 3569.87,2611.5 3629.28,2611.5 3654.1,2586.68 3700.83,2586.68 3725.22,2611.06 v1@3725.22,2613.9
MCU_GPIO45: EC1.92 U1.J13 | length 1597.4
  Top Layer w5: U1.J13@3631.55,2078.54 v2(3647.3,2062.79)
  Signal Layer 6 w5: v1(3903.44,2038.11) 3899.15,2038.11 3863,2001.96 3863,1929.85 3912.83,1880.02 3912.83,1764.27 v1(3958.83,1718.27)
  Bottom w5: EC1.92@3588.86,1135.27 3588.86,1228.57 3595.33,1235.04 3595.33,1352.3 3602.3,1359.27 3636.29,1359.27 3713.02,1436 3898,1436 4022.71,1560.71 4022.71,1666.57 3997.36,1691.91 3985.19,1691.91 v1(3958.83,1718.27) ; v2(3647.3,2062.79) 3662.8,2047.29 3745.13,2047.29 3751.63,2053.79 3887.76,2053.79 v1(3903.44,2038.11)
MCU_GPIO46: R31.2 R79.1 U1.F14 | length 977.2
  Top Layer w5: U1.F14@3663.05,2173.03 v2(3678.79,2188.77)
  Signal Layer 6 w5: v2(3678.79,2188.77) 3703.83,2213.81 3703.83,2375.72 3735.1,2407 3735.1,2494.9 3769.58,2529.38 3769.58,2591 3758,2602.58 v1(3758,2939)
  Bottom w5: R79.1@3620.32,2937.82 3631.5,2949 3690.69,2949 3718,2921.69 R31.2@3718,2920.62 3739.62,2920.62 v1(3758,2939)
MCU_GPIO47: U1.E14 | length 22.3
  Top Layer w5: U1.E14@3663.05,2204.52 v2(3678.79,2220.27)
MCU_GPIO48: EC1.99 U1.R16 | length 1206.9
  Top Layer w5: EC1.99@3714.84,1135.27 3714.84,1206.16 3702.25,1218.75 3702.25,1321.97 3757.54,1377.27 3983.21,1377.27 4022,1416.06 4022,1696.35 3971.35,1747 3925.57,1747 3784.3,1888.27 3727.33,1888.27 U1.R16@3726.04,1889.56
MCU_GPIO49: EC1.101 U1.P15 | length 1260.2
  Top Layer w5: U1.P15@3694.54,1921.06 3710.67,1904.94 3858.06,1904.94 3911.83,1851.17 3911.83,1831.98 4040,1703.81 4040,1408.6 3990.67,1359.27 3801.84,1359.27 3731,1288.42 3731,1243.1 3746.34,1227.76 EC1.101@3746.34,1135.27
MCU_GPIO50: EC1.103 U1.P14 | length 1378.4
  Top Layer w5: U1.P14@3663.05,1921.06 v2(3678.79,1905.31) ; EC1.103@3777.83,1135.27 3771.33,1141.77 3771.33,1265.77 v1(3780.83,1275.27)
  Signal Layer 6 w5: v1(3780.83,1275.27) 3780.83,1272.84 3771.83,1263.84 3771.83,1236.27 3785.33,1222.77 3834.06,1222.77 3846.58,1222.77 3896.5,1222.77 4064,1390.27 4064,1562 v1(4111,1609)
  Bottom w5: v2(3678.79,1905.31) 3759.69,1905.31 3892.08,1772.92 3958.16,1772.92 4060.26,1670.82 4060.26,1659.74 v1(4111,1609)
MCU_GPIO51: EC1.105 U1.N14 | length 994.5
  Top Layer w5: U1.N14@3663.05,1952.55 v2(3678.79,1936.81) ; v1(3784.93,1302.64) 3784.93,1302.17 3812.96,1274.14 3812.96,1138.89 EC1.105@3809.33,1135.27
  Signal Layer 6 w5: v1(3784.93,1302.64) 3784.93,1451.1 3860.32,1526.48 3860.32,1727.68 3843,1745 3843,1860 v1(3823,1880)
  Bottom w5: v2(3678.79,1936.81) 3766.19,1936.81 3799.97,1903.03 v1(3823,1880)
MCU_GPIO52: EC1.107 U1.N15 | length 1162.9
  Top Layer w5: U1.N15@3694.54,1952.55 3710.29,1936.81 3767.19,1936.81 3781.06,1922.94 3888.41,1922.94 3888.58,1922.77 3913.33,1922.77 3946.99,1889.11 v1(3963.03,1889.11) ; v1(3836.83,1276.27) 3836.83,1271.67 3831.41,1266.25 3831.41,1222.68 3840.83,1213.27 EC1.107@3840.83,1135.27
  Signal Layer 6 w5: v1(3836.83,1276.27) 3839.81,1276.27 3859.83,1296.29 3859.83,1306.83 4028,1475 4028,1727.82 3957.26,1798.57 3957.26,1884.34 v1@3955.33,1886.27
MCU_GPIO53: EC1.109 U1.N16 | length 983.8
  Top Layer w5: U1.N16@3726.04,1952.55 3813.85,1952.55 3819.4,1947 v1(3824,1947) ; v1(3831.83,1304.27) 3834.41,1301.69 3845.42,1301.69 3872.32,1274.79 EC1.109@3872.32,1135.27
  Signal Layer 6 w5: v1(3824,1947) 3824,1943.39 3886.62,1880.78 3886.62,1831.56 3869.32,1814.27 3869.32,1522.75 3832.57,1486.01 3832.57,1305.01 v1(3831.83,1304.27)
MCU_GPIO54: EC1.100 U1.M13 | length 1339.7
  Top Layer w5: U1.M13@3631.55,1984.05 v2(3647.3,1968.3) ; v1(3751,1342) 3777.27,1368.27 3986.94,1368.27 4031,1412.33 4031,1700.08 3869.12,1861.96 v1(3869.12,1868.69)
  Bottom w5: v2(3647.3,1968.3) 3662.74,1952.87 3672.31,1952.87 3672.37,1952.8 3685.21,1952.8 3685.28,1952.87 3784.94,1952.87 v1(3869.12,1868.69) ; EC1.100@3714.84,1135.27 3714.84,1305.84 v1(3751,1342)
MCU_GPIO55: EC1.102 U1.M14 | length 1335.2
  Top Layer w5: U1.M14@3663.05,1984.05 v2(3678.79,1968.3) ; v1(3750,1269) 3750,1294.7 3805.57,1350.27 3994.39,1350.27 4049,1404.87 4049,1707.53 3939.76,1816.78 v1@3939.76,1855.75
  Bottom w5: v2(3678.79,1968.3) 3833.45,1968.3 3934.8,1866.95 3934.8,1865.31 3939.76,1860.35 v1@3939.76,1855.75 ; EC1.102@3746.34,1135.27 3746.34,1260.74 3750,1264.4 v1(3750,1269)
  other v1: 3933.38,1859.84
MCU_GPIO56: EC1.104 U1.M15 | length 1241.2
  Top Layer w5: U1.M15@3694.54,1984.05 3710.29,1968.3 3860.64,1968.3 v1(3883.37,1945.57)
  Signal Layer 6 w5: v1(3794.83,1251.27) 3801.33,1257.77 3843.33,1257.77 3868.83,1283.27 3868.83,1303.1 4037,1471.27 4037,1844.1 3973.83,1907.27 3921.67,1907.27 v1(3883.37,1945.57)
  Bottom w5: EC1.104@3777.83,1135.27 3777.83,1234.27 v1(3794.83,1251.27)
MCU_GPIO57: EC1.106 U1.M16 | length 1293.6
  Top Layer w5: U1.M16@3726.04,1984.05 3876.8,1984.05 3951.08,1909.77 3969.57,1909.77 4038,1841.33 4038,1731.26 4058,1711.26 4058,1401.15 3998.12,1341.27 3828.89,1341.27 v1(3813.53,1325.9)
  Bottom w5: EC1.106@3809.33,1135.27 3809.33,1229.53 3815.07,1235.27 3815.07,1262.27 3807.83,1269.51 3807.83,1315.6 3813.53,1321.3 v1(3813.53,1325.9)
MCU_GPIO58: RJ1.12 U1.L13 | length 2427.3
  Top Layer w5: U1.L13@3631.55,2015.55 v2(3647.3,1999.8) ; RJ1.12@4903.31,2505.45 5001.01,2505.45 5007.06,2511.5 5007.06,2528.06 v1(5009,2530)
  Bottom w5: v2(3647.3,1999.8) 3662.74,1984.36 3672.31,1984.36 3672.37,1984.3 3685.21,1984.3 3685.28,1984.36 3876.49,1984.36 3913.33,1947.52 3913.33,1936.77 3942.83,1907.27 3985.85,1907.27 3994,1899.12 3994,1866.54 4072.78,1787.77 4475.6,1787.77 4598.37,1665 4703,1665 4727,1641 4761,1641 4919.5,1799.5 4919.5,2440.5 v1(5009,2530)
MCU_GPIO59: RJ2.12 U1.L14 | length 1419.6
  Top Layer w5: U1.L14@3663.05,2015.55 v2(3678.79,1999.8)
  Top Layer w6.25: v1(4748,1661) 4763.73,1645.27 4901.83,1645.27 RJ2.12@4903.31,1643.8
  Bottom w5: v2(3678.79,1999.8) 3873.78,1999.8 3922.33,1951.25 3922.33,1940.5 3946.56,1916.27 3989.58,1916.27 4003,1902.85 4003,1870.27 4076.5,1796.77 4479.33,1796.77 4602.1,1674 4735,1674 v1(4748,1661)
MCU_GPIO60: EC2.125 U1.L15 | length 1911.3
  Top Layer w5: U1.L15@3694.54,2015.55 3710.67,1999.42 3875.93,1999.42 3900.33,1975.02 3937.51,1937.84 v1(3954.35,1937.84) ; EC2.125@4919.47,1135.27 4919.47,1247.91 v1(4937.83,1266.27)
  Signal Layer 6 w5: v1(4773,1686) 4856.57,1602.43 4856.57,1285.79 4893.58,1248.77 4920.33,1248.77 v1(4937.83,1266.27)
  Bottom w5: v1(3954.35,1937.84) 3980.73,1937.84 4012,1906.58 4012,1874 4080.23,1805.77 4483.06,1805.77 4503.56,1785.27 4503.88,1785.27 4603.15,1686 v1(4773,1686)
MCU_GPIO61: EC2.126 U1.K16 | length 2046.8
  Top Layer w5: U1.K16@3726.04,2047.04 3800.06,2047.04 v1(3819.83,2027.27)
  Signal Layer 3 w5: v1(3819.83,2027.27) 3849.14,2056.58 4713.39,2056.58 4727.08,2070.27 v1(4728.83,2070.27)
  Signal Layer 6 w5: v1(4728.83,2070.27) 4733.43,2070.27 4738.34,2065.36 4740.08,2065.36 4809.88,1995.56 4874.57,1930.88 4874.57,1329.79 4901.83,1302.52 v1(4901.83,1302.27)
  Bottom w5: v1(4901.83,1302.27) 4919.83,1284.27 4919.83,1135.63 EC2.126@4919.47,1135.27
MCU_GPIO62: EC2.127 U1.K15 | length 2342.4
  Top Layer w5: U1.K15@3694.54,2047.04 3710.67,2030.92 3787.18,2030.92 v1(3790.83,2027.27) ; v1(4936.83,1304.27) 4955.33,1285.77 4955.33,1139.63 EC2.127@4950.97,1135.27
  Signal Layer 3 w5: v1(3790.83,2027.27) 3821.56,2058 3837.83,2058 3845.41,2065.58 4696.14,2065.58 4718.83,2088.27 4754.7,2088.27 4771.7,2071.27 5000.83,2071.27 5029.33,2042.77 5029.33,1972.77 v1(5017.83,1961.27)
  Signal Layer 6 w5: v1(4936.83,1304.27) 4936.83,1306.52 4954.33,1324.02 4954.33,1897.77 v1(5017.83,1961.27)
MCU_GPIO63: R158.1 R162.2 U1.K14 | length 1074.3
  Top Layer w5: U1.K14@3663.05,2047.04 v2(3678.79,2031.29) v2@3673.61,2036.48 ; v1(3850.83,2027.27) 3855.43,2027.27 3862.66,2020.04 3934.43,2020.04 3984.83,1969.64 3984.83,1928.7 3992.76,1920.77 4023.7,1920.77 4079.59,1976.66 4079.59,2140 4114.24,2174.64 4331.52,2174.64 4337.92,2181.04 R158.1@4337.92,2184.98 ; v1(4335.83,2229.27) 4335.83,2187.06 R158.1@4337.92,2184.98 ; R158.1@4340.83,2187.89 R158.1@4337.92,2184.98
  Bottom w5: v2(3678.79,2031.29) 3750.82,2031.29 3764.31,2044.79 3842.19,2044.79 3850.83,2036.15 v1(3850.83,2027.27) ; v1(4335.83,2229.27) 4335.95,2229.27 4348.44,2241.76 R162.2@4348.44,2266.7
MCU_GPIO64: R147.2 R150.1 U1.K13 | length 1132.4
  Top Layer w5: U1.K13@3631.55,2047.04 v2(3647.3,2031.29) ; v1(3947.45,1982.27) 3975.83,1953.89 3975.83,1924.97 3989.03,1911.77 4027.43,1911.77 4088.59,1972.93 4088.59,2134 4119.24,2164.64 4355.75,2164.64 4361.61,2170.5 4362.23,2170.5 R150.1@4380.44,2188.71 ; v1(4367.83,2229.27) 4372.43,2229.27 4381.19,2220.51 4381.7,2220.51 4385.23,2216.97 R150.1@4385.23,2190.29
  Bottom w5: v2(3647.3,2031.29) 3663.29,2015.3 3751.63,2015.3 3758.13,2008.8 3920.92,2008.8 v1(3947.45,1982.27) ; v1(4367.83,2229.27) 4367.83,2250.21 R147.2@4390,2272.38
MCU_GPIO65: EC2.130 U1.K12 | length 2382.7
  Top Layer w5: U1.K12@3600.06,2047.04 v2(3615.8,2031.29)
  Signal Layer 3 w5: v2(3615.8,2031.29) 3631.3,2046.79 3746.56,2046.79 3780.69,2012.66 3783.58,2009.77 3905.89,2009.77 3929.84,2033.73 4287.02,2033.73 4317.47,2003.27 5001.23,2003.27 5007.23,2009.27 v1(5011.83,2009.27)
  Signal Layer 6 w5: v1(4987.83,1325.58) 4987.83,1779.83 5036,1828 5036,1985.1 v1(5011.83,2009.27)
  Bottom w5: EC2.130@4982.46,1135.27 4982.46,1232.39 4968.71,1246.14 4968.71,1303.78 4987.83,1322.9 v1(4987.83,1325.58)
MCU_GPIO66: EC2.131 U1.K11 | length 2328.4
  Top Layer w5: U1.K11@3568.56,2047.04 v2(3584.31,2031.29) ; v1(4986.83,1296.27) 5013.96,1269.14 EC2.131@5013.96,1135.27
  Signal Layer 3 w5: v2(3584.31,2031.29) 3600.3,2015.3 3754.07,2015.3 3769.57,1999.8 3960.3,1999.8 3981.33,1978.77 4098.27,1978.77 4113.43,1963.61 4151.92,1963.61 4173.58,1985.27 4309.01,1985.27 4388.1,1906.19 4746.4,1906.19 4756.98,1916.77 4975.33,1916.77 v1(5015.83,1876.27)
  Signal Layer 6 w5: v1(4986.83,1296.27) 4963.33,1319.77 4963.33,1823.77 v1(5015.83,1876.27)
MCU_GPIO67: EC2.132 U1.D15 | length 2706.7
  Top Layer w5: U1.D15@3694.54,2236.02 3710.67,2252.14 3800.45,2252.14 3999.58,2451.27 4564.6,2451.27 4754.6,2261.27 4956.83,2261.27 5140.83,2077.27 5140.83,1436 5072.1,1367.27 v1(5034.83,1367.27)
  Bottom w5: EC2.132@5013.96,1135.27 5013.96,1346.4 v1(5034.83,1367.27)
MCU_GPIO68: EC2.133 U1.C16 | length 2658.5
  Top Layer w5: U1.C16@3726.04,2267.52 3791.08,2267.52 3860,2336.44 v1(3860,2357) ; v1@5037.13,1258.37 5037.13,1143.59 EC2.133@5045.46,1135.27
  Signal Layer 3 w5: v1(3860,2357) 3867.32,2364.32 4074.55,2364.32 4101.33,2337.54 4257.65,2337.54 4288.38,2368.27 4702.83,2368.27 4728.83,2394.27 v1(4992.83,2394.27)
  Signal Layer 6 w5: v1(4992.83,2394.27) 5001.83,2385.27 5001.83,2057.54 5036.33,2023.04 5054,2005.37 5054,1729 5014,1689 5014,1523.27 5014.33,1522.94 5014.33,1317.29 5014,1316.96 5014,1286.1 v1(5033.83,1266.27)
MCU_GPIO69: R148.1 U1.B16 | length 769.2
  Top Layer w5: U1.B16@3726.04,2299.01 3726.61,2299.59 3745.15,2299.59 v1(3812.83,2367.27) ; R148.1@4172.26,2040.56 4176.2,2040.56 4185.51,2049.87 4185.51,2050.48 4195.51,2060.48 4195.51,2117.72 v1(4177.16,2136.07)
  Bottom w5: v1(3812.83,2367.27) 3815.76,2367.27 3828.49,2380 4050,2380 4078.33,2351.67 4078.33,2251.77 4177.16,2152.94 v1(4177.16,2136.07)
MCU_GPIO70: R149.1 R161.2 U1.C15 | length 778.7
  Top Layer w5: U1.C15@3694.54,2267.52 3710.29,2283.26 3780.83,2283.26 v1(3783.83,2286.27) ; v1(4120,2136) 4120,2105.91 4136.47,2089.45 R149.1@4172.26,2089.45
  Bottom w5: v1(3783.83,2286.27) 3819.27,2286.27 3885.93,2352.93 4055.17,2352.93 4069.33,2338.77 4069.33,2248.04 4120,2197.37 v1(4120,2136) 4120.52,2135.48 4120.52,2099.63 R161.2@4129.83,2090.31
MCU_GPIO71: R130.1 R154.1 U1.B15 | length 1079
  Top Layer w5: U1.B15@3694.54,2299.01 3709.92,2314.39 3709.92,2345.67 3747.25,2383 v1(3749,2383) ; v1(4115.28,2004.44) 4155.56,2004.44 4168.32,1991.68 R154.1@4172.26,1991.68 ; R154.1@4180.88,1994.02 R154.1@4184.81,1994.02
  Signal Layer 3 w5: v1(3749,2383) 3791.27,2425.27 4108.4,2425.27 4124.4,2409.27 v1(4125.83,2409.27)
  Signal Layer 6 w5: v1(4115.28,2004.44) 4098.33,2021.4 4098.33,2218.97 4120.58,2241.22 4120.58,2268.92 4098.33,2291.17 4098.33,2381.52 4125.83,2409.02 v1(4125.83,2409.27)
  Bottom w5: v1(4115.28,2004.44) 4156.08,2004.44 4159.01,2001.51 4159.01,2000.99 4168.32,1991.68 R130.1@4172.26,1991.68
MCU_GPIO72: EC2.139 R62.1 U1.A15 | length 3617.4
  Top Layer w5: U1.A15@3694.54,2330.51 3695.77,2331.74 3695.77,2400.77 v1(3697,2402) ; EC2.139@5139.94,1135.27 5142.83,1138.15 v1(5142.83,1265.27)
  Signal Layer 3 w5: v1(3697,2402) 3700.18,2402 3741.44,2443.27 4234.1,2443.27 4247.6,2429.77 5161.81,2429.77 5315.81,2275.77 5487.33,2275.77 v1(5530.83,2232.27)
  Signal Layer 6 w5: v1(5142.83,1265.27) 5154.83,1253.27 5542.27,1253.27 5566.83,1277.83 5566.83,1861.17 5505.37,1922.63 5505.37,2206.8 v1(5530.83,2232.27)
  Bottom w5: R62.1@5487.44,2238.06 5493.23,2232.27 v1(5530.83,2232.27)
MCU_GPIO73: EC2.140 U1.D14 | length 2603.7
  Top Layer w5: U1.D14@3663.05,2236.02 v2(3678.79,2251.77)
  Signal Layer 3 w5: v1(3867.32,2255.76) 3867.32,2256.06 3884.53,2273.27 3947.83,2273.27 3960.83,2260.27 4028.72,2260.27 4056.63,2288.17 4847.93,2288.17 4870.83,2265.27 v1(5031.83,2265.27)
  Signal Layer 6 w5: v1(5031.83,2265.27) 5031.83,2209.54 5119,2122.37 5119,1344.1 v1(5140.83,1322.27)
  Bottom w5: v2(3678.79,2251.77) 3681.28,2254.25 3865.82,2254.25 v1(3867.32,2255.76) ; EC2.140@5139.94,1135.27 5139.94,1243.41 5119,1264.35 5119,1300.44 v1(5140.83,1322.27)
MCU_GPIO74: EC2.141 U1.C14 | length 2791.8
  Top Layer w5: U1.C14@3663.05,2267.52 v2(3678.79,2283.26) ; v1(5153,1294) 5171.44,1275.56 EC2.141@5171.44,1135.27
  Signal Layer 3 w5: v1(3810.58,2339.02) 3847.33,2375.77 4078.7,2375.77 4107.92,2346.54 4193.54,2346.54 4258.77,2411.77 5001,2411.77 5009.5,2403.27 v1(5034.83,2403.27)
  Signal Layer 6 w5: v1(5034.83,2403.27) 5034.83,2352.27 5078.37,2308.73 5078.37,2175.73 5128,2126.1 5128,1406.75 5162.56,1372.19 5162.56,1303.56 v1(5153,1294)
  Bottom w5: v2(3678.79,2283.26) 3754.83,2283.26 v1(3810.58,2339.02)
MCU_GPIO75: U1.B14
MCU_GPIO76: EC2.143 U1.A14 | length 2859.2
  Top Layer w5: U1.A14@3663.05,2330.51 3663.05,2365.48 v1(3675.83,2378.27) ; EC2.143@5202.94,1135.27 5202.94,1240.16 5194.33,1248.77 5194.33,1313.44 v1(5211.83,1330.94)
  Signal Layer 3 w5: v1(3675.83,2378.27) 3708.13,2378.27 3764.13,2434.27 4230.38,2434.27 4243.88,2420.77 5086.23,2420.77 v1(5110,2397)
  Signal Layer 6 w5: v1(5110,2397) 5132.83,2374.17 5132.83,2161.54 5216.83,2077.54 5216.83,1722.54 5194.33,1700.04 5194.33,1348.43 v1(5211.83,1330.94)
MCU_GPIO77: EC2.144 U1.F13 | length 2769.6
  Top Layer w5: U1.F13@3631.55,2173.03 v2(3647.3,2188.77)
  Signal Layer 3 w5: v1(3824.83,2217.27) 3824.83,2243.02 3864.08,2282.27 3951.56,2282.27 3964.56,2269.27 4025,2269.27 4052.9,2297.17 4851.65,2297.17 4864.64,2284.19 4981.57,2284.19 4981.65,2284.27 5092.32,2284.27 5099.32,2277.27 v1(5103.83,2277.27)
  Signal Layer 6 w5: v1(5103.83,2277.27) 5103.83,2165.08 5198.83,2070.08 5198.83,1730 5176.33,1707.5 5176.33,1307.77 v1(5211.83,1272.27)
  Bottom w5: v2(3647.3,2188.77) 3662.8,2204.27 3747.93,2204.27 3749.44,2202.77 3787.77,2202.77 3802.27,2217.27 v1(3824.83,2217.27) ; EC2.144@5202.94,1135.27 5202.94,1263.37 v1(5211.83,1272.27) ; v1@5212.83,1271.27 v1@5213.83,1272.27
MCU_GPIO78: EC2.128 U1.E13 | length 2531.9
  Top Layer w5: U1.E13@3631.55,2204.52 v2(3647.3,2220.27)
  Signal Layer 3 w5: v1(3852,2233) 3874.1,2233 3902.93,2204.17 4083.53,2204.17 4156.36,2277 4699.75,2277 4732.28,2244.47 4941.63,2244.47 v1(4963.83,2222.27)
  Signal Layer 6 w5: v1(4929,1340) 4929.96,1340 4944.33,1354.37 4944.33,2080.33 4963.83,2099.83 v1(4963.83,2222.27)
  Bottom w5: v2(3647.3,2220.27) 3663.29,2236.27 3747.93,2236.27 3751.63,2239.96 3796.03,2239.96 3801.23,2234.77 3850.23,2234.77 v1(3852,2233) ; v1(4929,1340) 4955.33,1313.67 4955.33,1135.27 EC2.128@4950.97,1135.27
MCU_GPIO79: EC2.146 U1.D13 | length 2830.3
  Top Layer w5: U1.D13@3631.55,2236.02 v2(3647.3,2251.77)
  Signal Layer 3 w5: v1(3886.83,2311.27) 3921.88,2346.32 4067.1,2346.32 4093.87,2319.54 4265.1,2319.54 4295.83,2350.27 4710.29,2350.27 4727.79,2367.77 5062.75,2367.77 v1(5076.83,2353.69)
  Signal Layer 6 w5: v1(5076.83,2353.69) 5076.83,2348.48 5103.12,2322.19 5123.83,2301.48 5123.83,2157.81 5207.83,2073.81 5207.83,1726.27 5185.33,1703.77 5185.33,1328.1 v1(5211.83,1301.6)
  Bottom w5: v2(3647.3,2251.77) 3662.8,2267.27 3685.21,2267.27 3685.28,2267.2 3842.77,2267.2 v1(3886.83,2311.27) ; v1(5211.83,1301.6) 5234.43,1279 EC2.146@5234.43,1135.27
MCU_GPIO80: EC2.147 U1.A13 | length 3073.4
  Top Layer w5: U1.A13@3631.55,2330.51 3631.55,2349.35 3639.05,2356.85 3639.05,2389.49 3703.32,2453.76 3714.45,2453.76 v1(3716.97,2456.27) ; EC2.147@5265.93,1135.27 5265.93,1254.37 v1(5283.83,1272.27)
  Signal Layer 3 w5: v1(3716.97,2456.27) 3729.7,2469 3790.62,2469 3794.85,2464.77 4238.54,2464.77 4253.04,2450.27 5186.9,2450.27 5199.9,2437.27 v1(5200.83,2437.27)
  Signal Layer 6 w5: v1(5200.83,2437.27) 5150.83,2387.27 5150.83,2169.54 5187,2133.37 5187,2132.83 5234.83,2085 5234.83,1715.08 5212.83,1693.08 5212.83,1384.02 5233.83,1363.02 5233.83,1322.27 v1(5283.83,1272.27)
MCU_GPIO81: EC2.148 U1.F12 | length 2774.2
  Top Layer w5: U1.F12@3600.06,2173.03 v2(3615.8,2188.77)
  Signal Layer 3 w5: v2(3615.8,2188.77) 3631.3,2173.27 3640.88,2173.27 3705.84,2173.27 3724.34,2154.77 3891.22,2154.77 3904.46,2168 4098.27,2168 4166.62,2236.35 4250.29,2236.35 4308.87,2177.77 4982.26,2177.77 4982.49,2178 5176.3,2178 5198.3,2156 v1(5202,2156)
  Signal Layer 6 w5: v1(5202,2156) 5278.83,2079.17 5278.83,1544.27 5276.83,1542.27 5251.83,1517.27 5251.83,1362.94 v1(5283.83,1330.94)
  Bottom w5: EC2.148@5265.93,1135.27 5265.93,1313.03 v1(5283.83,1330.94)
MCU_GPIO82: EC2.149 U1.E12 | length 2812
  Top Layer w5: U1.E12@3600.06,2204.52 v2(3615.8,2220.27) ; v1(5283.83,1360.27) 5302.33,1341.77 5302.33,1140.17 EC2.149@5297.43,1135.27
  Signal Layer 3 w5: v2(3615.8,2220.27) 3631.3,2204.77 3713.6,2204.77 3727.8,2190.57 3753.87,2164.5 3888.23,2164.5 3900.73,2177 4094.54,2177 4163.73,2246.19 4253.18,2246.19 4312.6,2186.77 4978.54,2186.77 4978.77,2187 5202,2187 5234.51,2154.49 v1(5234.51,2148.69)
  Signal Layer 6 w5: v1(5234.51,2148.69) 5240.31,2148.69 5288.83,2100.17 5288.83,1537.27 5260.83,1509.27 5260.83,1383.27 v1(5283.83,1360.27)
MCU_GPIO83: EC2.150 U1.D12 | length 3331.1
  Top Layer w5: U1.D12@3600.06,2236.02 v2(3615.8,2251.77)
  Signal Layer 3 w5: v1(3675,2468) 3675,2492.19 3694.58,2511.77 3776.04,2511.77 3784.04,2519.77 4006.52,2519.77 4031.52,2494.77 5219.33,2494.77 v1(5231.83,2482.27)
  Signal Layer 6 w5: v1(5231.83,2482.27) 5231.33,2481.77 5231.33,2438.77 5159.83,2367.27 5159.83,2173.27 5267.83,2065.27 5267.83,1546 5242.83,1521 5242.83,1342.6 v1(5283.83,1301.6) ; v1@5282.16,1299.94 v1@5283.83,1298.27
  Bottom w5: v2(3615.8,2251.77) 3631.3,2267.27 3631.3,2424.3 v1(3675,2468) ; v1(5283.83,1301.6) 5301.33,1284.1 5301.33,1139.17 EC2.150@5297.43,1135.27
MCU_GPIO84: EC2.151 R63.1 U1.D9 | length 3057.6
  Top Layer w5: U1.D9@3505.57,2236.02 v2@3520.87,2251.32 ; EC2.151@5328.92,1135.27 5328.92,1259.36 v1@5341.83,1272.27
  Signal Layer 3 w5: v2(3521.31,2251.77) 3536.81,2236.27 3685.21,2236.27 3694.83,2236.27 3724.68,2206.42 3743.67,2187.43 3788.82,2187.43 3802.75,2173.5 3884.5,2173.5 3897,2186 4090.82,2186 4160.59,2255.78 4256.32,2255.78 4316.32,2195.77 4974.81,2195.77 4975.04,2196 5224,2196 v1(5247,2173)
  Signal Layer 6 w5: v1(5247,2173) 5297.83,2122.17 5297.83,1529.27 5269.83,1501.27 5269.83,1451.54 5305.83,1415.54 5305.83,1304.27 v1(5337.83,1272.27)
  Bottom w5: R63.1@5180.44,2241.44 5182.88,2239 5182.88,2221.12 5231,2173 v1(5247,2173)
MCU_GPIO85: EC2.152 U1.C9 | length 3059.5
  Top Layer w5: U1.C9@3505.57,2267.52 v2(3521.31,2283.26)
  Signal Layer 3 w5: v2(3521.31,2283.26) 3543.82,2305.77 3865.33,2305.77 3879.83,2291.27 3955.29,2291.27 3968.29,2278.27 4021.27,2278.27 4049.17,2306.17 4264.46,2306.17 4297.29,2339 4872,2339 4888.81,2322.19 4932.58,2322.19 5069.17,2322.19 5069.58,2321.77 5084.08,2321.77 5084.5,2322.19 5231.91,2322.19 5310.83,2243.27 v1(5310.83,2240.27)
  Signal Layer 6 w5: v1(5310.83,2240.27) 5307.83,2237.27 5307.83,1526.54 5278.83,1497.54 5278.83,1455.27 5314.83,1419.27 5314.83,1353.94 v1(5337.83,1330.94)
  Bottom w5: EC2.152@5328.92,1135.27 5324.33,1139.86 5324.33,1257.02 5313.83,1267.52 5313.83,1306.94 v1(5337.83,1330.94)
MCU_GPIO86: EC2.153 U1.B9 | length 3589.8
  Top Layer w5: U1.B9@3505.57,2299.01 3521.69,2315.13 3521.69,2356.38 3556.33,2391.02 3556.33,2506.33 v1(3557,2507) ; v1@5343.83,1298.27 5360.42,1281.68 EC2.153@5360.42,1135.27
  Signal Layer 3 w5: v1(3557,2507) 3559.78,2507 3697.55,2644.77 4258.38,2644.77 4324.88,2578.27 5327.67,2578.27 5338.4,2589 v1(5343,2589)
  Signal Layer 6 w5: v1(5337.83,1301.6) 5358.37,1322.14 5358.37,2251.73 5326.94,2283.16 5326.94,2572.94 v1(5343,2589)
MCU_GPIO87: EC2.154 U1.A9 | length 3720.9
  Top Layer w5: v1(3491.63,2437.3) 3491.63,2436.77 3511.83,2416.57 3511.83,2362.36 3505.57,2356.1 U1.A9@3505.57,2330.51
  Signal Layer 3 w5: v1(3491.63,2437.3) 3501.86,2437.3 3514.83,2450.27 3514.83,2548.83 3577.5,2611.5 3648.35,2611.5 3690.62,2653.77 4520.08,2653.77 4533.08,2666.77 4716.6,2666.77 4770.36,2613 5288,2613 v1(5336,2661)
  Signal Layer 6 w5: v1(5333.47,1364.9) 5348.33,1379.76 5348.33,2249.04 5317.94,2279.44 5317.94,2642.94 v1(5336,2661)
  Bottom w5: v1(5333.47,1364.9) 5361.33,1337.05 5361.33,1136.18 EC2.154@5360.42,1135.27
